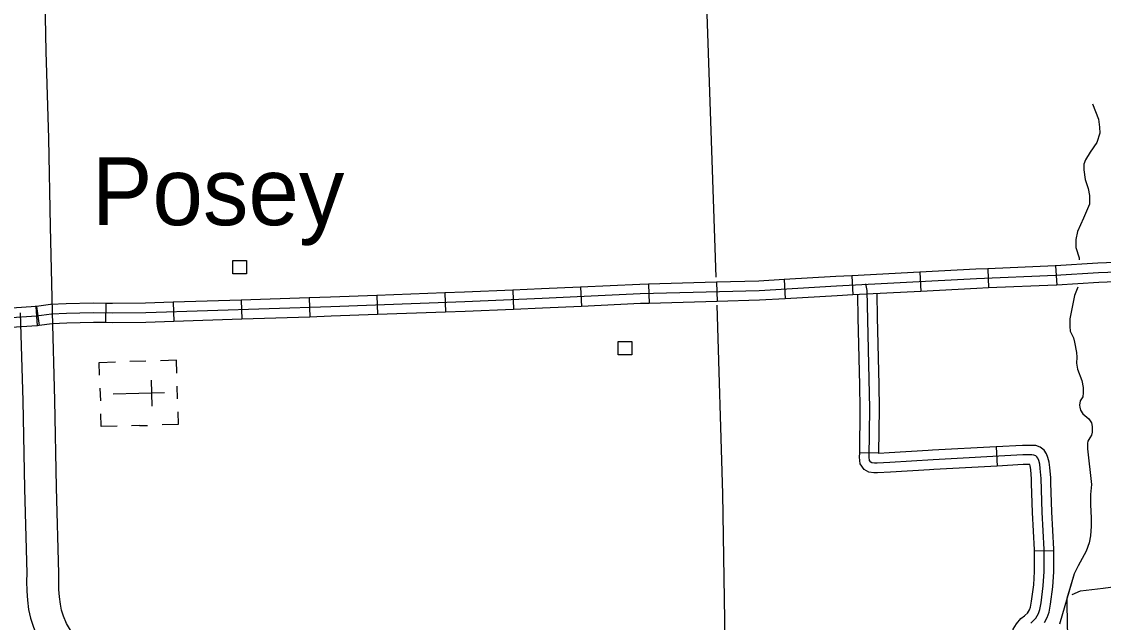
# Model space of a CAD drawing. Extents: x 1084508 to 1142749, y 1057638 to 1093403.
# Drawn here: x 1109281 to 1111920, y 1081818 to 1083285 of the extents above; entities that cross this region are included whole.
import ezdxf

# ---------------------------------------------------------------- set-up
doc = ezdxf.new("R2010")
doc.units = 0
for name, color, linetype in [('Level 10', 7, 'Continuous'), ('Level 24', 7, 'Continuous'), ('Level 32', 7, 'Continuous'), ('Level 35', 7, 'Continuous'), ('Level 43', 7, 'Continuous'), ('Level 45', 7, 'Continuous'), ('Level 47', 7, 'Continuous'), ('Level 5', 7, 'Continuous'), ('Level 56', 7, 'Continuous'), ('Level 57', 7, 'Continuous')]:
    doc.layers.add(name, color=color, linetype=linetype)

msp = doc.modelspace()

# ---------------------------------------------------------------- linework, layer by layer
at = {"layer": 'Level 10'}
for points in [[(1109663, 1081405.5), (1109660.5, 1081409.3), (1109524.6, 1081611.9), (1109415, 1081775.7), (1109400.2, 1081799.4), (1109390.6, 1081815.2), (1109383.4, 1081833), (1109378.4, 1081848.3), (1109375.5, 1081862.3), (1109373.4, 1081880.3), (1109372, 1081898.7), (1109371.4, 1081919.5), (1109371.7, 1081937.8), (1109366.2, 1082147.2), (1109361.9, 1082360.8), (1109356.2, 1082575.9), (1109351.6, 1082784.7), (1109347.3, 1082999.3), (1109340.9, 1083211.7), (1109336.6, 1083422.6)], [(1109277.7, 1082574), (1109283.5, 1082358.9), (1109287.8, 1082145.4), (1109293.2, 1081937.5), (1109292.9, 1081919.1), (1109293.6, 1081894.7), (1109295.3, 1081872.7), (1109298, 1081849.7), (1109302.5, 1081828.1), (1109309.7, 1081806.1), (1109320.2, 1081779.9), (1109333.3, 1081758.3), (1109349.1, 1081733.1), (1109459.4, 1081568.2), (1109595.3, 1081365.6), (1109597.8, 1081361.9)]]:
    msp.add_lwpolyline(points, dxfattribs=at)
at = {"layer": 'Level 32'}
for p, q in [((1111471.8, 1082673.3), (1111474.3, 1082626.3)), ((1111637.6, 1082681.7), (1111639.5, 1082634.7)), ((1111802.7, 1082688.6), (1111805.6, 1082641.6)), ((1110975.8, 1082648.7), (1110977.1, 1082601.6)), ((1111140.7, 1082655.1), (1111143.4, 1082608.1)), ((1111306.3, 1082664.6), (1111308.8, 1082617.5)), ((1110313.2, 1082622.7), (1110314.9, 1082575.7)), ((1110478.7, 1082629.5), (1110480.7, 1082582.4)), ((1110644.2, 1082636.8), (1110646.3, 1082589.8)), ((1110810.2, 1082644.1), (1110811.5, 1082597)), ((1109486.1, 1082597.1), (1109485.6, 1082550.1)), ((1109650.8, 1082599.7), (1109652.3, 1082552.7)), ((1109816.4, 1082605.2), (1109818, 1082558.2)), ((1109982.1, 1082610.7), (1109983.6, 1082563.7)), ((1110147.6, 1082616.6), (1110149.3, 1082569.6)), ((1109315.6, 1082589.4), (1109318.7, 1082542.4)), ((1109317.3, 1082589.6), (1109323.7, 1082543))]:
    msp.add_line(p, q, dxfattribs=at)
for points in [[(1111999, 1082675), (1111907.5, 1082671.5), (1111802.9, 1082665), (1111609.8, 1082657), (1111268.7, 1082639), (1111080.1, 1082628), (1110789.4, 1082620), (1110550.3, 1082609), (1110362.2, 1082601), (1110035, 1082588.9), (1109583.8, 1082573.9), (1109502.2, 1082573.4), (1109455.7, 1082573.9), (1109390.2, 1082572.4), (1109353.6, 1082570.9), (1109317.2, 1082565.9)], [(1111471.8, 1082673.3), (1111306.3, 1082664.6)], [(1111637.6, 1082681.7), (1111608.7, 1082680.5), (1111471.8, 1082673.3)], [(1111802.7, 1082688.6), (1111801.7, 1082688.5), (1111637.6, 1082681.7)], [(1111968.7, 1082697.4), (1111906.3, 1082695), (1111802.7, 1082688.6)], [(1110975.8, 1082648.7), (1110810.2, 1082644.1)], [(1111140.7, 1082655.1), (1111079, 1082651.5), (1110975.8, 1082648.7)], [(1111306.3, 1082664.6), (1111267.3, 1082662.5), (1111140.7, 1082655.1)], [(1111970.5, 1082650.4), (1111908.7, 1082648), (1111805.6, 1082641.6)], [(1110313.2, 1082622.7), (1110147.6, 1082616.6)], [(1110478.7, 1082629.5), (1110361.2, 1082624.5), (1110313.2, 1082622.7)], [(1110644.2, 1082636.8), (1110549.2, 1082632.5), (1110478.7, 1082629.5)], [(1110810.2, 1082644.1), (1110788.5, 1082643.5), (1110644.2, 1082636.8)], [(1111474.3, 1082626.3), (1111308.8, 1082617.5)], [(1111639.5, 1082634.7), (1111610.9, 1082633.5), (1111474.3, 1082626.3)], [(1111805.6, 1082641.6), (1111804.2, 1082641.5), (1111639.5, 1082634.7)], [(1109486.1, 1082597.1), (1109455.6, 1082597.5), (1109389.4, 1082596), (1109351.5, 1082594.4), (1109317.3, 1082589.6)], [(1109650.8, 1082599.7), (1109583.3, 1082597.5), (1109502.3, 1082597), (1109486.1, 1082597.1)], [(1109816.4, 1082605.2), (1109650.8, 1082599.7)], [(1109982.1, 1082610.7), (1109816.4, 1082605.2)], [(1110147.6, 1082616.6), (1110034.2, 1082612.5), (1109982.1, 1082610.7)], [(1110811.5, 1082597), (1110790.3, 1082596.4), (1110646.3, 1082589.8)], [(1110977.1, 1082601.6), (1110811.5, 1082597)], [(1111143.4, 1082608.1), (1111081.1, 1082604.5), (1110977.1, 1082601.6)], [(1111308.8, 1082617.5), (1111270, 1082615.5), (1111143.4, 1082608.1)], [(1109317.2, 1082565.9), (1109022.7, 1082546.2)], [(1109315.6, 1082589.4), (1109150.2, 1082578.3)], [(1109317.3, 1082589.6), (1109313.9, 1082589.2)], [(1110149.3, 1082569.6), (1110035.8, 1082565.4), (1109983.6, 1082563.7)], [(1110314.9, 1082575.7), (1110149.3, 1082569.6)], [(1110480.7, 1082582.4), (1110363.1, 1082577.4), (1110314.9, 1082575.7)], [(1110646.3, 1082589.8), (1110551.3, 1082585.4), (1110480.7, 1082582.4)], [(1109318.7, 1082542.4), (1109153.4, 1082531.4)], [(1109323.7, 1082543), (1109320.4, 1082542.5)], [(1109485.6, 1082550.1), (1109455.8, 1082550.4), (1109390.9, 1082548.9), (1109355.7, 1082547.4), (1109323.7, 1082543)], [(1109652.3, 1082552.7), (1109584.2, 1082550.4), (1109502.2, 1082549.9), (1109485.6, 1082550.1)], [(1109818, 1082558.2), (1109652.3, 1082552.7)], [(1109983.6, 1082563.7), (1109818, 1082558.2)]]:
    msp.add_lwpolyline(points, dxfattribs=at)
at = {"layer": 'Level 35'}
for points in [[(1111893.2, 1083084.4), (1111907.9, 1083046.5), (1111910, 1083026.9), (1111910.7, 1083012.9), (1111903.7, 1082989.8), (1111887.6, 1082966), (1111875.7, 1082947.8), (1111872.2, 1082937.2), (1111871.5, 1082923.2), (1111875, 1082899.4), (1111882.7, 1082877.7), (1111885.5, 1082860.2), (1111885.5, 1082839.2), (1111870.8, 1082804.8), (1111856.1, 1082772.6), (1111852.6, 1082753), (1111852.6, 1082733.4), (1111860.3, 1082707.9), (1111860.3, 1082703.5)], [(1111857.1, 1082637), (1111849.1, 1082616.1), (1111837.9, 1082559.3), (1111837.9, 1082540.4), (1111838.6, 1082529.2), (1111846.3, 1082513.1), (1111849.1, 1082502.6), (1111854, 1082477.4), (1111854.7, 1082465.4), (1111854, 1082451.4), (1111856.8, 1082436), (1111867.1, 1082408.4), (1111870.6, 1082391.6), (1111870.6, 1082378.3), (1111869.2, 1082369.2), (1111862.9, 1082358.7), (1111861.5, 1082348.2), (1111862.2, 1082343.3), (1111864.1, 1082336.1), (1111869.7, 1082327.7), (1111884.4, 1082315.4), (1111890.4, 1082305.3), (1111892.5, 1082296.5), (1111892.1, 1082282.5), (1111890.7, 1082275.1), (1111886.9, 1082268.5), (1111881.6, 1082260.4), (1111880.6, 1082255.5), (1111880.6, 1082242.2), (1111890.7, 1082154.6), (1111888.5, 1082130.4), (1111887.8, 1082105.6), (1111889.9, 1082072.6), (1111889.6, 1082052.7), (1111888.2, 1082029.6), (1111885, 1082012.7), (1111877.3, 1081992.4), (1111858.4, 1081956.3), (1111847.9, 1081936.4)], [(1111830.6, 1081876.7), (1111831.5, 1081806), (1111856, 1081554.5), (1111868.3, 1081266.2), (1111858.1, 1081215), (1111841.7, 1081196.6), (1111788.9, 1081190.6)]]:
    msp.add_lwpolyline(points, dxfattribs=at)
at = {"layer": 'Level 43'}
for points in [[(1111847.9, 1081936.4), (1111812.4, 1081813.7)], [(1111847.9, 1081936.4), (1111830.6, 1081876.7)]]:
    msp.add_lwpolyline(points, dxfattribs=at)
at = {"layer": 'Level 45'}
for p, q in [((1111372.2, 1082231.5), (1111325.2, 1082232.1)), ((1111657.9, 1082246.9), (1111660.5, 1082199.9)), ((1111798.5, 1081992.6), (1111751.5, 1081992.3))]:
    msp.add_line(p, q, dxfattribs=at)
for points in [[(1111742.8, 1081816.5), (1111754.8, 1081828.2), (1111760.9, 1081839.5), (1111764.4, 1081849.4), (1111767.4, 1081866), (1111772.9, 1081907.5), (1111775.3, 1081942.1), (1111775, 1081996.2), (1111770.5, 1082087.4), (1111767.8, 1082169.3), (1111765.7, 1082194), (1111764.4, 1082204.6), (1111762, 1082213.5), (1111759.9, 1082219), (1111757.5, 1082222.7), (1111754.4, 1082225.1), (1111750.3, 1082226.5), (1111744.8, 1082226.9), (1111723.1, 1082226.9), (1111504.5, 1082215.1), (1111398.6, 1082208.7), (1111367.9, 1082206.7), (1111361.5, 1082206.7), (1111355.1, 1082207.7), (1111351.9, 1082209.4), (1111349.2, 1082213.4), (1111348.6, 1082221.9), (1111350.1, 1082340.4), (1111343.7, 1082628.5), (1111340.3, 1082644.5)], [(1111368.7, 1082563.7), (1111367.4, 1082620.6)], [(1111321.6, 1082562.6), (1111320.3, 1082618.1)], [(1111325.3, 1082397), (1111321.6, 1082562.6)], [(1111372.3, 1082398), (1111368.7, 1082563.7)], [(1111325.2, 1082232.1), (1111326.5, 1082340.2), (1111325.3, 1082397)], [(1111372.2, 1082231.5), (1111373.6, 1082340.5), (1111372.3, 1082398)], [(1111791.7, 1082158.8), (1111791.3, 1082170.7), (1111789.1, 1082196.4), (1111787.5, 1082209.2), (1111784.4, 1082220.7), (1111781.1, 1082229.5), (1111775.2, 1082238.8), (1111765.7, 1082246.2), (1111754.9, 1082249.8), (1111745.6, 1082250.4), (1111722.5, 1082250.4), (1111657.9, 1082246.9)], [(1111495.1, 1082191), (1111400, 1082185.2), (1111368.6, 1082183.2), (1111359.7, 1082183.2), (1111347.5, 1082185.1), (1111335.7, 1082191.4), (1111326.2, 1082205.3), (1111325, 1082221.2), (1111325.2, 1082232.1)], [(1111492.3, 1082237.9), (1111397.1, 1082232.2), (1111372.2, 1082230.6), (1111372.2, 1082231.5)], [(1111657.9, 1082246.9), (1111503.1, 1082238.6), (1111492.3, 1082237.9)], [(1111660.5, 1082199.9), (1111505.8, 1082191.6), (1111495.1, 1082191)], [(1111744.6, 1082157.3), (1111744.3, 1082167.9), (1111742.3, 1082191.5), (1111741.2, 1082200), (1111740.3, 1082203.3), (1111723.7, 1082203.3), (1111660.5, 1082199.9)], [(1111751.5, 1081992.3), (1111751.4, 1081995.6), (1111747, 1082086.4), (1111744.6, 1082157.3)], [(1111798.5, 1081992.6), (1111798.5, 1081996.9), (1111794, 1082088.4), (1111791.7, 1082158.8)], [(1111734.8, 1081840.7), (1111739.3, 1081849), (1111741.5, 1081855.5), (1111744.2, 1081869.7), (1111749.5, 1081909.8), (1111751.8, 1081942.8), (1111751.5, 1081992.3)], [(1111776.1, 1081818.2), (1111782.5, 1081830), (1111787.2, 1081843.4), (1111790.7, 1081862.3), (1111796.4, 1081905.1), (1111798.9, 1081941.3), (1111798.5, 1081992.6)], [(1111668.9, 1081683.8), (1111669.6, 1081695.5), (1111669.6, 1081707.8), (1111670.8, 1081718.8), (1111672.3, 1081729.2), (1111675, 1081741.7), (1111688.8, 1081774.4), (1111699.4, 1081801.4), (1111707.6, 1081814.7), (1111718.5, 1081827.5), (1111727.3, 1081834.3), (1111735.8, 1081842.6), (1111734.8, 1081840.7)]]:
    msp.add_lwpolyline(points, dxfattribs=at)
at = {"layer": 'Level 47'}
msp.add_lwpolyline([(1111843.3, 1081886.1), (1111863.6, 1081895.5), (1111919.4, 1081901.7), (1112027.1, 1081916)], dxfattribs=at)
at = {"layer": 'Level 5'}
for points in [[(1110920.8, 1084232.2), (1110974.3, 1082660.8)], [(1110976.5, 1082592.7), (1110990.2, 1082132), (1110997.4, 1081670.9)]]:
    msp.add_lwpolyline(points, dxfattribs=at)
at = {"layer": 'Level 56'}
for points in [[(1109796.3, 1082669.3), (1109796.3, 1082702), (1109829, 1082702), (1109829, 1082669.3)], [(1110736.2, 1082471), (1110736.2, 1082503.7), (1110769, 1082503.7), (1110769, 1082471)]]:
    msp.add_lwpolyline(points, close=True, dxfattribs=at)
at = {"layer": 'Level 57'}
for p, q in [((1109583.8, 1082456), (1109544.6, 1082455)), ((1109597.1, 1082409.3), (1109598.8, 1082346.2)), ((1109472, 1082390.1), (1109472.9, 1082358.7)), ((1109661.1, 1082363.7), (1109660.3, 1082395.1)), ((1109629.3, 1082378.7), (1109503.8, 1082375.4)), ((1109566.6, 1082377.1), (1109566.6, 1082377.1)), ((1109566.6, 1082377.1), (1109566.6, 1082377.1)), ((1109568.7, 1082298.6), (1109548.8, 1082298.1)), ((1109568.7, 1082298.6), (1109588, 1082299.1))]:
    msp.add_line(p, q, dxfattribs=at)
for points in [[(1109471.2, 1082421.6), (1109470.4, 1082453), (1109509.6, 1082454)], [(1109659.5, 1082426.6), (1109658.6, 1082458), (1109619.4, 1082457)], [(1109662, 1082332.5), (1109662.8, 1082301.1), (1109623.6, 1082300.1)], [(1109513.8, 1082297.1), (1109474.5, 1082296.1), (1109473.7, 1082327.5)]]:
    msp.add_lwpolyline(points, dxfattribs=at)

# ---------------------------------------------------------------- texts
at = {"layer": 'Level 24'}
msp.add_text('Posey', height=165.73, dxfattribs=at).set_placement((1109452.1, 1082788))

doc.saveas('drawing.dxf')
